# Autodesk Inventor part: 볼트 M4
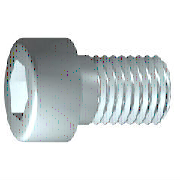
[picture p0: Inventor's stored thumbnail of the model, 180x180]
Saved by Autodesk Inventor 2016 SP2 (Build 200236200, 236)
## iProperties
IsCustomPart: 1
Created: 2015-10
Part Number: 볼트 M4
Material: 스테인리스강
Description: 6각머리 태핑 나사
Document SubType Name: Modeling
Standard: KS B 1003
Designer: mdu
Standards Organization: KS
Language: ko-KR
Size Designation: M 4 x 16
Categories: <MemberInstance><Categories><Category DisplayName="조임쇠" InternalName="e4da775c-781d-43d5-af7c-5136215cf5a6" Mnemonic="FSTN"><Category DisplayName="볼트" InternalN
Density: 8.08 g/cm^3
Mass: 2.70334 g
Surface Area: 3.81118 cm^2
Volume: 0.334572 cm^3
Appearance: 반광택
Author: mdu
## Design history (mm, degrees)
sketch "스케치1"
  geometry: L1 (-1, 0)-(16, 0); L2 (16, 0)-(16, 2); L3 (16, 2)-(1.75, 2); L4 (1.75, 2)-(1.32, 2); L5 (1.32, 2)-(0, 2); L6 (0, 2)-(0, 3.5); L7 (0, 3.5)-(-4, 3.5); L8 (-4, 3.5)-(-4, 1.732); L9 (-4, 1.732)-(-2, 1.732); L10 (-2, 1.732)-(-1, 0); L11 (-8, 0)-(20, 0) reference; L12 (0, -0.7)-(0, 4.2) reference; L13 (1.75, 2)-(0, 2)
  constraints: 22 end point, 6 parallel, 2 collinear, 2 perpendicular, 1 horizontal, 1 point on line
  dimensions: "d1" = 14.25 distance from line of L3.end L2 (= GEL); "d2" = 0.42952 distance of L4.end L3.end (computed from GAL); "d3" = 4 distance between parallel lines of L8 L6 (= KOH); "d4" = 2 distance of L8.end L9.end (= INTI); "d5" = 60 deg angle of L10 L1; "d6" = 4 diameter of L3 L1 (= GD); "d7" = 4 diameter of L5 L1 (= BDM); "d8" = 3.4641 diameter of L9 L1 (= 1.1547 x SW); "d9" = 7 diameter of L7 L1 (= KOD); "d26" = 16 distance between parallel lines of L12 L2 (= NLG)
revolve "본체" sketch "스케치1" stored, may be unused: angle "d10" = 90 deg
sketch "스케치2"
  geometry: L1 (0, -4.9)-(0, 4.9) reference; L2 (-4.9, 0)-(4.9, 0) reference; L3 (1.732, 0)-(0.866, -1.5); L4 (0.866, -1.5)-(-0.866, -1.5); L5 (-0.866, -1.5)-(-1.732, 0); L6 (-1.732, 0)-(-0.866, 1.5); L7 (-0.866, 1.5)-(0.866, 1.5); L8 (0.866, 1.5)-(1.732, 0); 2 further points
  constraints: 12 end point, 1 coincident, 1 horizontal alignment, 1 point on line, 12 other
extrude "슬롯" join sketch "스케치2" stored distance "d11" = 10; taper "d12" = 0 deg
workplane "Work Plane1"
fillet "Fillet2" dims "d30" = 0.1 (= R)
body "Solid1"
fillet "모깎기1" dims "d17" = 0.4 (= RR)
feature "스레드" dims "d13" = 14.25 (= GEL), "d14" = 0
chamfer "모따기1" distance "d15" = 0.42941 (= -0.5 x SPD + 0.5 x GD); stored, may be unused: second distance "d16" = 0.42941 (= GUL), angle "d27" = 45 deg
other parameters: "GD" = 4 (= NND) [user parameter; used in 2 equation terms], "NLG" = 16 [user parameter; used in 1 equation term], "GEL" = 14.25 [user parameter; used in 2 equation terms], "KOD" = 7 [user parameter; used in 1 equation term], "KOH" = 4 [user parameter; used in 1 equation term], "INTI" = 2 [user parameter; used in 1 equation term], "GAL" = 0.42941 (= 0.61345 x PTC) [user parameter; used in 1 equation term], "GUL" = 0.42941 (= 0.61345 x PTC) [user parameter; used in 1 equation term], "BDM" = 4 (= NND) [user parameter; used in 1 equation term], "SW" = 3 [user parameter; used in 2 equation terms], "RR" = 0.4 [user parameter; used in 1 equation term], "SPD" = 3.14117 (= NND - 1.2269 x PTC) [user parameter; used in 1 equation term], "d19" = 0, "d28" = 0, "d29" = 0, "R" = 0.1 [user parameter; used in 1 equation term], "PHH" = 0.2 [user parameter], "GD1" = 3.14117 (= THREADDIA - 1.2269 x PTC) [user parameter], "THREADDIA" = 4 [user parameter; used in 1 equation term], "FAWI" = 45 deg [user parameter], "TPU" = 14.28571 (computed from PTC) [user parameter], "PTC" = 0.7 [user parameter; used in 5 equation terms], "NND" = 4 [user parameter; used in 3 equation terms], "TOA" = 30 deg [user parameter], "E0" = 3.465 (= 1.155 x SW) [user parameter]
